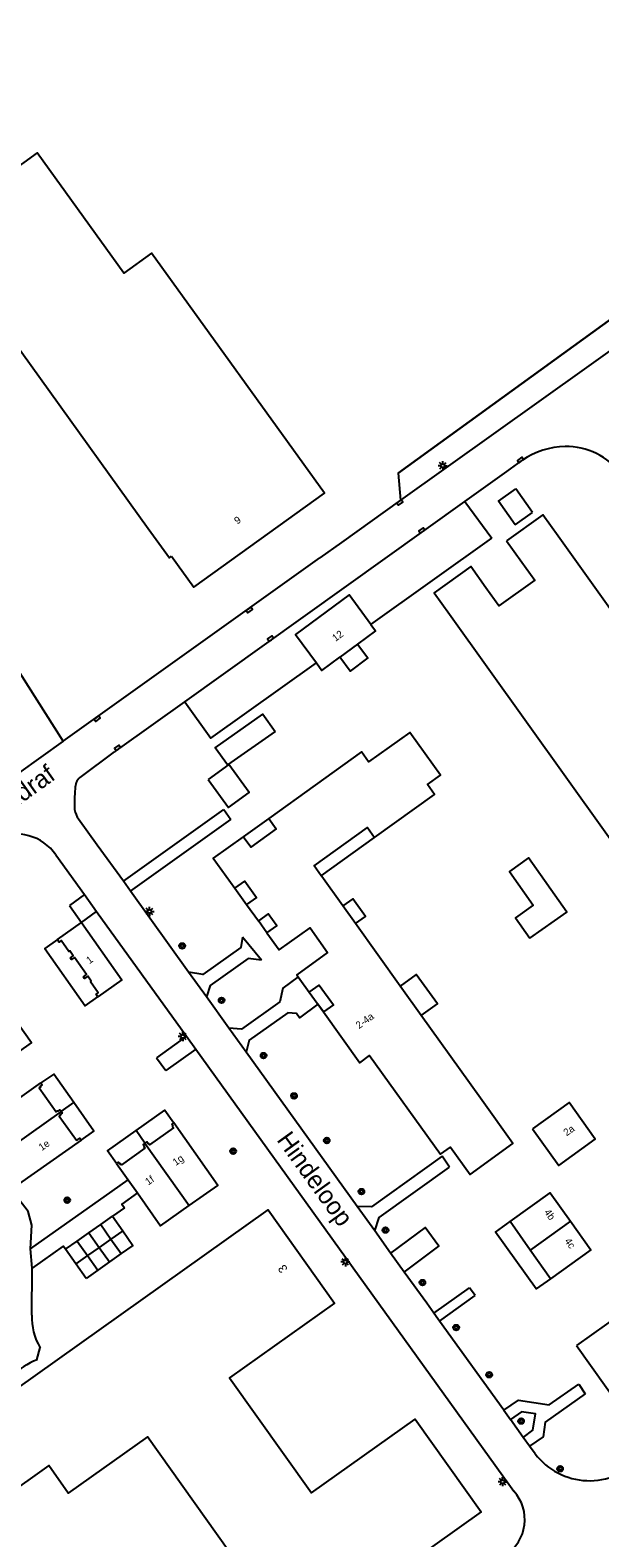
# Model space of a CAD drawing. Extents: x 141000 to 143000, y 400580 to 403500.
# Drawn here: x 141149.1 to 141228, y 403024.1 to 403232.7 of the extents above; entities that cross this region are included whole.
import ezdxf

# ---------------------------------------------------------------- set-up
doc = ezdxf.new("R2010")
doc.units = 0
for name, color, linetype in [('gg-afsc-erfafscheiding', 7, 'Continuous'), ('gg-afsc-hekwerk', 7, 'Continuous'), ('gg-anno-huisnummerreeks BGT', 7, 'Continuous'), ('gg-anno-openbare ruimte label', 7, 'Continuous'), ('gg-bbg-bijgebouw', 7, 'Continuous'), ('gg-bbg-hoofdgebouw', 7, 'Continuous'), ('gg-bbg-luifel en loopbrug', 7, 'Continuous'), ('gg-bbg-overig bouwwerk', 7, 'Continuous'), ('gg-bbg-tussenscheiding', 7, 'Continuous'), ('gg-knt-verharding', 7, 'Continuous'), ('gg-knt-verharding nz', 7, 'Continuous'), ('gt-anno-plantopografie huisnummer', 7, 'Continuous'), ('gt-bbg-plantopografie pand', 7, 'Continuous'), ('gt-grn-groengrens', 7, 'Continuous'), ('gt-grn-vlakafsluiter', 7, 'Continuous'), ('gt-symb-boom', 7, 'Continuous'), ('gt-symb-kolk', 7, 'Continuous'), ('gt-symb-lichtmast', 7, 'Continuous'), ('gx-grn-maaiveld', 7, 'Continuous')]:
    doc.layers.add(name, color=color, linetype=linetype)

# ---------------------------------------------------------------- blocks, each defined once
blk = doc.blocks.new('gt0-BOOM')
at = {"layer": 'gt-symb-boom'}
for radius in [0.4, 0.2]:
    blk.add_circle((0, 0), radius, dxfattribs=at)
blk = doc.blocks.new('gt0-LMAST')
at = {"layer": 'gt-symb-lichtmast'}
for p, q in [((-0.18, 0.17), (-0.45, 0.44)), ((-0.01, 0.25), (-0.01, 0.62)), ((0.17, 0.17), (0.44, 0.44)), ((-0.26, 0), (-0.63, 0)), ((-0.18, -0.18), (-0.45, -0.45)), ((-0.01, -0.25), (-0.01, -0.63)), ((0.44, -0.45), (0.17, -0.18)), ((0.24, 0), (0.62, 0))]:
    blk.add_line(p, q, dxfattribs=at)
blk.add_circle((-0.01, 0), 0.25, dxfattribs=at)
blk = doc.blocks.new('gt0-KOLK')
at = {"layer": 'gt-symb-kolk'}
blk.add_lwpolyline([(0, 0), (0.37, 0), (0.37, 0.4), (-0.38, 0.4), (-0.38, 0), (0, 0)], dxfattribs=at)

msp = doc.modelspace()

# ---------------------------------------------------------------- linework, layer by layer
at = {"layer": 'gg-afsc-erfafscheiding'}
msp.add_line((141216.6, 403172.75), (141217.24, 403173.21), dxfattribs=at)
at = {"layer": 'gg-afsc-hekwerk'}
for p, q in [((141175.9, 403124.87), (141176.87, 403123.51)), ((141210.69, 403057.6), (141209.9, 403058.7))]:
    msp.add_line(p, q, dxfattribs=at)
msp.add_lwpolyline([(141200.03, 403171.43), (141232.86, 403195.18), (141285.62, 403232.74)], dxfattribs=at)
at = {"layer": 'gg-bbg-bijgebouw'}
for p, q in [((141157.2, 403066.3), (141158.83, 403067.44)), ((141158.83, 403067.44), (141160.45, 403068.59)), ((141160.45, 403068.59), (141161.88, 403066.57)), ((141153.96, 403064.02), (141155.58, 403065.16)), ((141155.58, 403065.16), (141157.2, 403066.3)), ((141155.38, 403062), (141153.96, 403064.02)), ((141161.68, 403063.41), (141160.06, 403062.27)), ((141156.81, 403059.98), (141155.38, 403062)), ((141158.43, 403061.12), (141156.81, 403059.98)), ((141160.06, 403062.27), (141158.43, 403061.12))]:
    msp.add_line(p, q, dxfattribs=at)
for points in [[(141183.01, 403135.69), (141176.38, 403131.04), (141174.68, 403133.41), (141181.3, 403138.07), (141183.01, 403135.69)], [(141218.29, 403107.08), (141223.38, 403110.66), (141218.09, 403118.18), (141215.45, 403116.32), (141218.76, 403111.62), (141216.31, 403109.89), (141218.29, 403107.08)], [(141161.88, 403066.57), (141163.3, 403064.55), (141161.68, 403063.41)]]:
    msp.add_lwpolyline(points, dxfattribs=at)
at = {"layer": 'gg-bbg-hoofdgebouw'}
for p, q in [((141194.41, 403147.78), (141191.95, 403145.97)), ((141179.03, 403111.73), (141180.67, 403109.45)), ((141194.11, 403109.09), (141192.37, 403111.53)), ((141152.83, 403106.87), (141156.16, 403109.25)), ((141200.32, 403100.43), (141194.11, 403109.09)), ((141186.2, 403101.72), (141187.73, 403099.59)), ((141203.23, 403096.36), (141200.32, 403100.43)), ((141156.14, 403079.11), (141147.46, 403073.02)), ((141161.02, 403075.91), (141162.63, 403073.62)), ((141162.63, 403073.62), (141163.91, 403071.81)), ((141218.34, 403063.9), (141215.53, 403067.86)), ((141221.15, 403059.94), (141218.34, 403063.9))]:
    msp.add_line(p, q, dxfattribs=at)
for points in [[(141168.64, 403159.92), (141171.75, 403155.66), (141189.82, 403168.68), (141165.89, 403201.89), (141162.04, 403199.11), (141150.05, 403215.75), (141135.52, 403205.28), (141165.43, 403163.76), (141168.38, 403159.73), (141168.64, 403159.92)], [(141256.29, 403077.65), (141241.49, 403067.07), (141250.45, 403054.54), (141282.98, 403077.8), (141245.4, 403130.28), (141240.39, 403126.69), (141238.66, 403129.1), (141243.67, 403132.69), (141222.2, 403162.69), (141220.07, 403165.66), (141215.06, 403162.08)], [(141215.06, 403162.08), (141217.18, 403159.11), (141218.96, 403156.62), (141213.98, 403153.06), (141212.2, 403155.55), (141210.1, 403158.49), (141205.03, 403154.86), (141207.13, 403151.93), (141250.06, 403091.97), (141252.56, 403093.76), (141261.45, 403081.34), (141258.75, 403079.42)], [(141196.23, 403150.5), (141193.24, 403154.57), (141185.82, 403149.11), (141188.72, 403145.17)], [(141196.23, 403150.5), (141196.89, 403149.61), (141194.41, 403147.78)], [(141188.72, 403145.17), (141189.47, 403144.14), (141191.95, 403145.97)], [(141196.78, 403121), (141205.07, 403126.94), (141204.08, 403128.32), (141205.91, 403129.63), (141201.66, 403135.56), (141195.94, 403131.46), (141194.95, 403132.85), (141182.1, 403123.65)], [(141182.1, 403123.65), (141183.13, 403122.2), (141179.62, 403119.65), (141178.58, 403121.11)], [(141189.38, 403115.7), (141188.39, 403117.08), (141195.79, 403122.38), (141196.78, 403121)], [(141178.58, 403121.11), (141174.43, 403118.14), (141177.4, 403114)], [(141192.37, 403111.53), (141189.45, 403115.6), (141189.38, 403115.7)], [(141177.4, 403114), (141178.78, 403114.98), (141180.41, 403112.72), (141179.03, 403111.73)], [(141156.16, 403109.25), (141161.78, 403101.3), (141158.44, 403098.94)], [(141181.86, 403107.79), (141183.24, 403108.78), (141182.05, 403110.44), (141180.67, 403109.45)], [(141158.44, 403098.94), (141158.19, 403099.3), (141158.48, 403099.52), (141157.41, 403101.04), (141157.52, 403101.12), (141157.04, 403101.8), (141156.61, 403101.49), (141156.45, 403101.72), (141156.88, 403102.03), (141155.19, 403104.41), (141154.78, 403104.11), (141154.63, 403104.34), (141155.04, 403104.63), (141154.56, 403105.3), (141154.44, 403105.23), (141153.37, 403106.75), (141153.07, 403106.54), (141152.83, 403106.87)], [(141181.86, 403107.79), (141183.54, 403105.44), (141187.83, 403108.5), (141190.26, 403105.1), (141185.98, 403102.02), (141186.2, 403101.72)], [(141187.73, 403099.59), (141189.11, 403100.59), (141191.06, 403097.86), (141189.68, 403096.87)], [(141189.68, 403096.87), (141194.72, 403089.84), (141196.08, 403090.84), (141205.9, 403077.17), (141207.28, 403078.16), (141210, 403074.38), (141215.93, 403078.65), (141211.65, 403084.62), (141209.9, 403087.05), (141203.23, 403096.36)], [(141144.69, 403076.97), (141141.91, 403080.92), (141150.56, 403087.03)], [(141150.56, 403087.03), (141150.74, 403086.79), (141150.47, 403086.6), (141150.52, 403086.52), (141150.33, 403086.38), (141152.67, 403083.05), (141152.87, 403083.19), (141152.92, 403083.12), (141153.19, 403083.31), (141153.34, 403083.07)], [(141218.65, 403080.68), (141222.27, 403075.63), (141227.33, 403079.25), (141223.71, 403084.31), (141218.65, 403080.68)], [(141153.34, 403083.07), (141153.49, 403082.84), (141153.23, 403082.66), (141153.28, 403082.58), (141153.09, 403082.44), (141155.46, 403079.1), (141155.65, 403079.23), (141155.68, 403079.22), (141155.93, 403079.4), (141156.14, 403079.11)], [(141168.96, 403081.52), (141168.67, 403081.34), (141168.84, 403081.07), (141168.77, 403081.02), (141168.9, 403080.82), (141165.61, 403078.47), (141165.47, 403078.66), (141165.4, 403078.61), (141165.22, 403078.88), (141164.96, 403078.71)], [(141171.09, 403070.07), (141175.08, 403072.86), (141168.96, 403081.52)], [(141164.96, 403078.71), (141164.71, 403078.53), (141164.9, 403078.27), (141164.83, 403078.22), (141164.96, 403078.03), (141161.66, 403075.67)], [(141161.66, 403075.67), (141161.52, 403075.87), (141161.44, 403075.82), (141161.26, 403076.06), (141161.02, 403075.91)], [(141163.91, 403071.81), (141167.1, 403067.27), (141171.09, 403070.07)], [(141215.53, 403067.86), (141221.11, 403071.85), (141223.91, 403067.89)], [(141223.91, 403067.89), (141226.72, 403063.93), (141221.15, 403059.94)], [(141224.76, 403050.7), (141230.81, 403042.21), (141239.11, 403048.12), (141236.21, 403052.2), (141233.06, 403056.61), (141224.76, 403050.7)]]:
    msp.add_lwpolyline(points, dxfattribs=at)
at = {"layer": 'gg-bbg-luifel en loopbrug'}
for p, q in [((141182.1, 403123.65), (141178.58, 403121.11)), ((141189.38, 403115.7), (141196.78, 403121)), ((141177.4, 403114), (141179.03, 403111.73)), ((141181.86, 403107.79), (141180.67, 403109.45)), ((141187.73, 403099.59), (141189.68, 403096.87)), ((141153.34, 403083.07), (141155.11, 403084.31)), ((141164.96, 403078.71), (141163.75, 403080.46))]:
    msp.add_line(p, q, dxfattribs=at)
for points in [[(141194.41, 403147.78), (141195.83, 403145.85), (141193.38, 403144.04), (141191.95, 403145.97)], [(141173.71, 403129.02), (141176.54, 403125.14), (141179.4, 403127.23), (141176.58, 403131.11), (141173.71, 403129.02)], [(141194.11, 403109.09), (141195.49, 403110.08), (141193.75, 403112.52), (141192.37, 403111.53)], [(141152.83, 403106.87), (141151.08, 403105.63), (141156.69, 403097.7), (141158.44, 403098.94)], [(141203.23, 403096.36), (141205.47, 403097.97), (141202.55, 403102.03), (141200.32, 403100.43)], [(141147.49, 403091.36), (141149.25, 403092.6), (141146.45, 403096.57)], [(141155.11, 403084.31), (141152.32, 403088.26), (141150.56, 403087.03)], [(141156.14, 403079.11), (141157.9, 403080.35), (141155.11, 403084.31)], [(141163.75, 403080.46), (141167.73, 403083.26), (141168.96, 403081.52)], [(141161.02, 403075.91), (141159.78, 403077.66), (141163.75, 403080.46)], [(141221.15, 403059.94), (141219.16, 403058.56), (141213.52, 403066.4), (141215.53, 403067.86)]]:
    msp.add_lwpolyline(points, dxfattribs=at)
at = {"layer": 'gg-bbg-overig bouwwerk'}
for p, q in [((141218.66, 403165.97), (141216.34, 403169.26)), ((141216.26, 403164.27), (141218.66, 403165.97))]:
    msp.add_line(p, q, dxfattribs=at)
msp.add_lwpolyline([(141216.26, 403164.27), (141213.94, 403167.57), (141216.34, 403169.26)], dxfattribs=at)
at = {"layer": 'gg-bbg-tussenscheiding'}
for p, q in [((141153.34, 403083.07), (141144.69, 403076.97)), ((141164.96, 403078.71), (141171.09, 403070.07)), ((141158.83, 403067.44), (141160.25, 403065.43)), ((141223.91, 403067.89), (141218.34, 403063.9)), ((141155.58, 403065.16), (141157.01, 403063.14)), ((141157.2, 403066.3), (141158.63, 403064.28)), ((141160.25, 403065.43), (141158.63, 403064.28)), ((141161.88, 403066.57), (141160.25, 403065.43)), ((141160.25, 403065.43), (141161.68, 403063.41)), ((141157.01, 403063.14), (141155.38, 403062)), ((141158.63, 403064.28), (141157.01, 403063.14)), ((141157.01, 403063.14), (141158.43, 403061.12)), ((141158.63, 403064.28), (141160.06, 403062.27))]:
    msp.add_line(p, q, dxfattribs=at)
at = {"layer": 'gg-knt-verharding'}
for p, q in [((141287.67, 403230), (141200.35, 403167.68)), ((141209.29, 403167.53), (141215.07, 403171.66)), ((141215.07, 403171.66), (141216.6, 403172.75)), ((141170.47, 403139.79), (141209.29, 403167.53)), ((141200.35, 403167.68), (141192.18, 403161.84)), ((141209.29, 403167.53), (141213.02, 403162.44)), ((141192.18, 403161.84), (141189.17, 403159.69)), ((141196.23, 403150.5), (141213.02, 403162.44)), ((141161.5, 403133.39), (141170.47, 403139.79)), ((141155.97, 403129.33), (141160.76, 403132.84)), ((141161.97, 403114.94), (141175.9, 403124.87)), ((141162.95, 403113.57), (141176.87, 403123.51)), ((141152.63, 403118.59), (141156.59, 403113.1)), ((141156.59, 403113.1), (141154.49, 403111.61)), ((141156.59, 403113.1), (141158.27, 403110.77)), ((141162.95, 403113.57), (141161.97, 403114.94)), ((141171, 403102.39), (141162.95, 403113.57)), ((141156.16, 403109.25), (141158.27, 403110.77)), ((141158.27, 403110.77), (141170.7, 403093.51)), ((141170.7, 403093.51), (141166.56, 403090.53)), ((141170.7, 403093.51), (141171.99, 403091.72)), ((141171.99, 403091.72), (141167.85, 403088.74)), ((141194.38, 403069.92), (141179, 403091.28)), ((141149.09, 403064.08), (141160.4, 403072.06)), ((141198.99, 403063.5), (141196.8, 403066.55)), ((141149.36, 403061.41), (141149.09, 403064.08)), ((141200.89, 403060.87), (141198.99, 403063.5)), ((141149.28, 403054.91), (141149.36, 403061.41)), ((141204.98, 403055.18), (141209.9, 403058.7)), ((141205.78, 403054.08), (141210.69, 403057.6)), ((141214.67, 403041.73), (141205.78, 403054.08)), ((141150.01, 403048.72), (141150.45, 403050.4)), ((141217.37, 403037.98), (141215.59, 403040.45)), ((141219, 403035.71), (141218.24, 403036.77))]:
    msp.add_line(p, q, dxfattribs=at)
for points in [[(141170.47, 403139.79), (141174.08, 403134.76), (141188.72, 403145.17)], [(141161.97, 403114.94), (141158.35, 403119.96), (141155.78, 403123.53)], [(141178.46, 403107.19), (141178.23, 403105.76), (141172.98, 403102.06), (141171, 403102.39)], [(141181.1, 403104.05), (141179.28, 403104.25), (141173.99, 403100.51), (141173.48, 403098.95)], [(141186.2, 403101.72), (141184.04, 403100.16), (141183.66, 403098.24), (141178.35, 403094.47), (141176.6, 403094.62)], [(141189.68, 403096.87), (141188.93, 403097.92), (141186.36, 403096.07), (141185.97, 403096.64), (141184.74, 403096.73), (141179.38, 403092.94), (141179, 403091.28)], [(141171.99, 403091.72), (141215.37, 403031.51), (141216.08, 403030.52)], [(141149.09, 403064.08), (141149.3, 403067.33), (141148.8, 403069.23), (141147.56, 403070.86), (141131.42, 403087.43)], [(141206.13, 403076.9), (141196.35, 403069.88), (141194.38, 403069.92)], [(141196.8, 403066.55), (141197.4, 403068.41), (141207.17, 403075.4)], [(141163.91, 403071.81), (141161.74, 403070.28), (141162.11, 403069.76)], [(141200.89, 403060.87), (141205.67, 403064.43), (141203.78, 403067.03), (141198.99, 403063.5)], [(141153.96, 403064.02), (141153.65, 403064.45), (141149.36, 403061.41)], [(141204.98, 403055.18), (141204, 403056.55), (141200.89, 403060.87)], [(141205.78, 403054.08), (141205.55, 403054.39), (141204.98, 403055.18)], [(141214.67, 403041.73), (141216.72, 403043.14), (141220.96, 403042.48), (141225.05, 403045.37)], [(141225.95, 403044.02), (141220.4, 403040.09), (141220.13, 403038.08), (141218.24, 403036.77)], [(141217.37, 403037.98), (141218.69, 403038.97), (141219.05, 403041.22), (141217.11, 403041.54), (141215.59, 403040.45)]]:
    msp.add_lwpolyline(points, dxfattribs=at)
for centre, radius, start, end in [((141223.41, 403164.27), 10.86, 91.3239, 124.6201), ((141223.25, 403165.47), 9.66, 37.2203, 90.507), ((141167.08, 403125.09), 10, 123.9098, 129.2106), ((141180.9, 403125.67), 25.7, 175.3941, 181.7498), ((141157.26, 403127.84), 1.97, 130.7011, 183.0055), ((141158.24, 403125.34), 3.05, 188.6641, 216.4615), ((141147.02, 403114.65), 6.86, 35.0308, 113.3003), ((141157.56, 403054.64), 8.28, 178.1412, 210.8254), ((141154.64, 403037.5), 12.14, 112.4125, 131.8589), ((141226.55, 403041.5), 9.51, 217.4885, 317.7465), ((141211.72, 403026.61), 5.86, 303.4572, 41.8905)]:
    msp.add_arc(centre, radius, start, end, dxfattribs=at)
at = {"layer": 'gg-knt-verharding nz'}
for p, q in [((141181.1, 403104.05), (141178.46, 403107.19)), ((141173.48, 403098.95), (141171, 403102.39)), ((141176.6, 403094.62), (141173.48, 403098.95)), ((141179, 403091.28), (141176.6, 403094.62)), ((141207.17, 403075.4), (141206.13, 403076.9)), ((141196.8, 403066.55), (141194.38, 403069.92)), ((141214.67, 403041.73), (141215.59, 403040.45)), ((141218.24, 403036.77), (141217.37, 403037.98))]:
    msp.add_line(p, q, dxfattribs=at)
at = {"layer": 'gt-bbg-plantopografie pand'}
for points in [[(141103.5, 403026.08), (141126.6, 403042.51), (141129.76, 403038.07), (141144.33, 403048.44), (141147.07, 403044.6), (141182.03, 403069.48), (141191.21, 403056.56), (141176.68, 403046.23), (141188.02, 403030.29), (141202.4, 403040.52), (141211.54, 403027.68), (141185.2, 403008.94)], [(141176.6, 403022.24), (141165.33, 403038.08), (141154.34, 403030.27), (141151.63, 403034.08), (141133.43, 403021.13)]]:
    msp.add_lwpolyline(points, dxfattribs=at)
at = {"layer": 'gt-grn-groengrens'}
msp.add_lwpolyline([(141285.62, 403232.74), (141232.86, 403195.18), (141200.03, 403171.43)], dxfattribs=at)
at = {"layer": 'gt-grn-vlakafsluiter'}
for p, q in [((141200.03, 403171.43), (141200.35, 403167.68)), ((141154.49, 403111.61), (141156.16, 403109.25)), ((141166.56, 403090.53), (141167.85, 403088.74)), ((141160.4, 403072.06), (141162.63, 403073.62)), ((141162.11, 403069.76), (141160.45, 403068.59)), ((141225.05, 403045.37), (141225.95, 403044.02))]:
    msp.add_line(p, q, dxfattribs=at)
at = {"layer": 'gx-grn-maaiveld'}
for q in [(141093.07, 403229.33), (141189.17, 403159.69), (141140.88, 403125.24)]:
    msp.add_line((141153.65, 403134.34), q, dxfattribs=at)

# ---------------------------------------------------------------- block references
at = {"layer": 'gt-symb-boom'}
for p in [(141170.12, 403105.99), (141175.58, 403098.47), (141181.4, 403090.82), (141185.61, 403085.24), (141177.18, 403077.6), (141190.14, 403079.07), (141194.95, 403071.99), (141154.2, 403070.81), (141198.29, 403066.67), (141203.4, 403059.41), (141208.07, 403053.17), (141212.65, 403046.66), (141217.06, 403040.24), (141222.46, 403033.64)]:
    msp.add_blockref('gt0-BOOM', p, dxfattribs=at)
at = {"layer": 'gt-symb-kolk'}
for p, rotation in [((141217.09, 403173.1), 36.760145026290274), ((141200.15, 403167.53), -144.4810837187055), ((141203.42, 403163.33), 35.54143033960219), ((141179.3, 403152.65), -144.4810837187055), ((141182.49, 403148.38), 35.54143033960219), ((141158.24, 403137.61), -144.4810837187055), ((141161.28, 403133.24), 35.36224959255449)]:
    msp.add_blockref('gt0-KOLK', p, dxfattribs=dict(at, rotation=rotation))
at = {"layer": 'gt-symb-lichtmast'}
for p in [(141206.22, 403172.45), (141165.6, 403110.77), (141170.21, 403093.47), (141192.73, 403062.27), (141214.51, 403031.84)]:
    msp.add_blockref('gt0-LMAST', p, dxfattribs=at)

# ---------------------------------------------------------------- texts
at = {"layer": 'gg-anno-huisnummerreeks BGT'}
for s, rotation, p in [('9', 35.7, (141177.77, 403164.31)), ('12', 36.7, (141191.36, 403148.07)), ('1', 35.3, (141157.27, 403103.46)), ('2-4a', 35.7, (141194.61, 403094.47)), ('2a', 35.6, (141223.37, 403079.63)), ('1e', 35.4, (141150.67, 403077.59)), ('1g', 35.6, (141169.24, 403075.53)), ('1f', 35.5, (141165.43, 403072.83)), ('4b', 305.3, (141220.2, 403069.15)), ('4c', 305.3, (141223.03, 403065.15))]:
    msp.add_text(s, height=1, rotation=rotation, dxfattribs=at).set_placement(p)
at = {"layer": 'gg-anno-openbare ruimte label'}
for s, rotation, p in [('Paardendraf', 35.5, (141137.77, 403118.49)), ('Hindeloop', 305.8, (141183.13, 403079.15))]:
    msp.add_text(s, height=2.5, rotation=rotation, dxfattribs=at).set_placement(p)
at = {"layer": 'gt-anno-plantopografie huisnummer'}
msp.add_text('3', height=1.2, rotation=125.4317, dxfattribs=at).set_placement((141184.79, 403061.29))

doc.saveas('drawing.dxf')
